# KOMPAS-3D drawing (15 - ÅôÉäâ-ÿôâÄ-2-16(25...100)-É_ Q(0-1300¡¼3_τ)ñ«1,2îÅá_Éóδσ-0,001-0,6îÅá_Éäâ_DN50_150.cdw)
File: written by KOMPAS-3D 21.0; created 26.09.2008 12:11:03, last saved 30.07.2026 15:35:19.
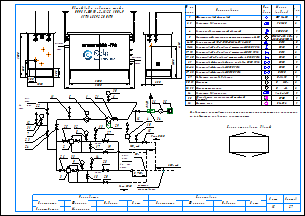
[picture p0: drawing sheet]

Sheets 1-2: A3, landscape

Document properties: Наименование: Макро:21; Автор: RaskoAdmin; Форматы листов документа: 2xA3; Полное имя файла: \\ur38nt01\Departments\КТО\КБ ПУРДГ\Заявки\Прайс-лист на типовые шкафы ГРПШ\ПУРДГ_стандарт_30_04_2026\ПУРДГ с РДГ(Н, В)\ПУРДГ-ШУГО-2-16(25...100)-Р_ Q(0-1300нм3_ч)до1,2МПа_Рвых-0,001-0,6МПа_РДГ_DN50_150.cdw

Title block, sheet 1: Наименование: Пункт учета газа / ПУГ-Ш-400-Р / ЛГТИ.485922.001ТУ; designation: ЛГТИ.03.4411141; sheet number: 1; Количество листов документа: 2; organisation: ООО "ЭЛЬСТЕР Газэлектроника"; Форматы листов документа: A3; stored path: C:\Рабочие документы\Компас\ПУГ\Схема.cdw; Разработал: Устинов; Проверил: Кошкин; Утвердил: Кошкин
Title block, sheet 2: sheet number: 2; stored path: D:\Рабочие документы\Заявки\ПУРДГ\ПУРДГ-ШУЭО-2-100-Р 4411220.cdw; designation, second copy: ЛГТИ.03.4411141-

Views: Вид 1, Вид 2
Referenced files: wcvoit.frw
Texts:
  Normal
  № на
  схеме
  Усл.
  обозн.
  Марка
  (модель)
  Кол.
  Фильтр газовый фланцевый
  ФГ 16-50
  Регулятор давления газа
  РДГ-50
  Клапан предохранительный сбросной
  КПС DN20
  Измерительный комплекс с ротационным счетчиком Ду50
  СГ-ЭК-Р-(0,2...2,0)-
  Кран кнопочный VE-РАСКО-НЗ-1,6-G1/2-М20
  DN15
  Кран шаровой "под приварку" штуцерный DN20 PN16
  DN20
  Кран шаровой "под приварку" штуцерный DN15 PN16
  Кран шаровой "под приварку" штуцерный п/п DN20 PN16
  Кран шаровой фланцевый с мех. приводом DN50 PN16
  Кран шаровой фланцевый DN50 PN16
  Кран шаровой фланцевый DN150 PN16
  DN50
  DN150
  Индикатор перепада давления
  Манометр
  Манометр-напоромер
  Обогреватель газогорелочный шкафной
  (Эльтон")
  Счетчик газа
  Delta 15
  0...     МПа
  0...     кПа
  Venio-A-15
  ОГШН
  BK-G1,6
  Общий вид и габариты шкафа
  ПУРДГ-ШУГО-2-16(25...100)-Р
  Выход газа
  Вход газа
  logo-rasko-ge.png
  DN 1
  местное
  сопротивление
  Римп DN20
  Выход
  газа
  Р=     кПа
  Вход
  Р=       МПа
  PDI
  Схема открывания дверей
  Предприятие изготовитель может заменять комплектующие на аналогичные,
  не ухудшающие заявленных характеристик.
  Должность
  Конструктор
  Фамилия
  Подпись
  Дата
  Согласовано
  Максимкин
  Лист
  Листов
  POLYLINE_STYLE_0.18_RGB_0_0_0
  POLYLINE_STYLE_0.50_RGB_0_0_0
  POLYLINE_STYLE_0.34_RGB_0_0_0
  PHANTOM_RGB_0_0_0_SC_1_THICK_0.18
  K5LT_THIN_RGB_0_0_0_THICK_0.18
  K5LT32769_RGB_0_0_0_THICK_0.18
  K5LT12_RGB_0_0_0_SC_1_THICK_0.18
  K5LT_DASHED_RGB_0_0_0_SC_1_THICK_0.18
  ACISOTGL_RGB_0_0_0_SC_0.8_THICK_0.25
  CONTINUOUS_RGB_0_127_31_THICK_0.3
  CONTINUOUS_RGB_0_0_255_THICK_0.35
  CONTINUOUS_RGB_255_0_0_THICK_0.35
  POLYLINE_STYLE_0.25_RGB_0_0_0
  CONTINUOUS_RGB_0_0_0_THICK_0.5
  POLYLINE_STYLE_0.35_RGB_0_0_255
  CONTINUOUS_RGB_0_0_0_THICK_0.4
  CONTINUOUS_RGB_0_0_0_THICK_0.35
  НЕВИДИМАЯ_RGB_0_0_0_SC_0.3_THICK_0.25
  СONTINUOUS_RGB_0_0_0_THICK_0.25
  ОСЕВАЯ2_RGB_248_153_30_SC_0.3_THICK_0.25
  Без оформления
Dimensions and other numbers on the sheet: 1; 2, 3; 2; 4; 5; 6-10; 11-16; 17, 18; 19, 20; 21; 22-26; 27, 28; 29; 30, 31; 32, 33; 34; 35; 36; 1500; 250; 300; 1050; 550; 305; 3000; 4130; 2000; 3300; 5,,,7DN 1; 7; 31; 12; 22; 23; 24; 11; 6; 30; 25; 32; 8; 13; 27; 19; 10; 15; 26; 33; 9; 3; 14; 28; 20; 17; 18; 16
